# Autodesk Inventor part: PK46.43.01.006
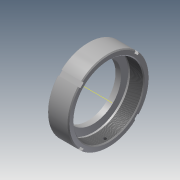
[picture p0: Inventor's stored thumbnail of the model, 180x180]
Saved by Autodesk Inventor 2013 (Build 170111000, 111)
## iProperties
Shininess: 64.0
Length Units: 11269
Angle Units: 11279
Time Units: 11290
Mass Units: 11283
Length Display Precision: 3
Angle Display Precision: 2
Compacted: True
Part Number: PK46.43.01.006
Document SubType Name: Modeling
Created: 2004-11
Material: Steel, High Strength Low Alloy
Designer: ELarisa
Manufacturer: Standard
Standards Organization: Custom
Density: 7.84 g/cm^3
Density: 0.0
Volumn: 0.0
Area: 0.0
PropertySet Name: Model Information
Control State: 0
Master: False
Checked Out: False
Checked Out Date: 2008-10-09
Last Check In Date: 2008-10-09
Author: ELarisa
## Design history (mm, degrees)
revolve "Вращение1" stored, may be unused: angle "d8" = 90 deg
chamfer "Фаска1" distance "d9" = 2; stored, may be unused: second distance "d10" = 2, angle "d40" = 45 deg
feature "Резьба2" dims "d13" = 10, "d14" = 0
chamfer "Фаска2" distance "d15" = 2; stored, may be unused: second distance "d16" = 2, angle "d41" = 45 deg
node "РабОсь1"
node "РабПлоскость1"
sketch "Эскиз2"
  geometry: L1 (-24.211, 0)-(145.265, 0) reference; L2 (2, 87.5)-(2, -87.5) reference; 2 further points
  dimensions: "d18" = 0 distance from line of L1 point (37, 0); "d19" = 35 distance from line of L2 point (37, 0)
hole "Отверстие1" sketch "Эскиз2" at (37, 0), (121.054, 48.551) diameter "d20" = 6.647; stored, may be unused: countersink angle "d24" = 82 deg, drill point angle "d26" = 118 deg; dims "d21" = 15, "d22" = 11.2, "d23" = 2, "d25" = 20
sketch "Эскиз3"
  geometry: L1 (0, 0)-(0, -97.588); L2 (0, 0)-(-81.792, -81.792); L3 (-65.407, -65.407)-(-68.943, -61.872); L4 (-68.943, -61.872)-(-61.872, -54.801); L5 (-61.872, -54.801)-(-54.801, -61.872); L6 (-54.801, -61.872)-(-61.872, -68.943); L7 (-61.872, -68.943)-(-65.407, -65.407); C1 r 60 at (0, 0) reference; C2 r 85.5 at (0, 0) reference
  constraints: 14 end point, 3 perpendicular, 2 parallel, 2 point on line, 1 vertical
  dimensions: "d27" = 45 deg angle of L2 L1; "d29" = 82.5 distance from line of C1.centre L5; "d31" = 10 distance of L5.end L6.end; "d32" = 5 distance of L6.end L7.end; "d33" = 5 distance of L3.start L3.end; "d34" = 10 distance of L3.end L4.end
extrude "Выдавливание1" cut sketch "Эскиз3" stored distance "d35" = 10; taper "d36" = 0 deg
pattern_circular "Круговой массив1" dims angle "d39" = 360 deg
body "Solid1"
sketch "Эскиз1"
  geometry: L1 (0, 0)-(0, 87.5); L2 (0, 87.5)-(46, 87.5); L3 (46, 87.5)-(46, 0); L4 (46, 0)-(0, 0); L5 (0, 60)-(12, 60); L6 (12, 60)-(12, 75.5); L7 (12, 75.5)-(16, 75.5); L8 (16, 75.5)-(16.5, 75); L9 (16.5, 75)-(46, 75)
  constraints: 18 end point, 4 parallel, 3 perpendicular, 2 point on line, 1 vertical, 1 other
  dimensions: "d0" = 46 distance of L3.end L1.start; "d1" = 87.5 distance of L1.start L1.end; "d2" = 75.5 distance from line of L6.end L4; "d3" = 60 distance between parallel lines of L4 L5; "d4" = 75 distance between parallel lines of L4 L9; "d5" = 34 distance between parallel lines of L3 L6; "d6" = 4 distance of L6.end L7.end; "d7" = 135 deg angle of L9 L8
other parameters: "d17" = -87.5
